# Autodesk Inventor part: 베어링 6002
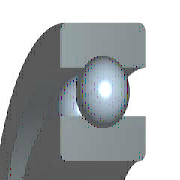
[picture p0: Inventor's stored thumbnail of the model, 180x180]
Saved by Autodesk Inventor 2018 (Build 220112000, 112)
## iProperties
IsCustomPart: 0
Created: 2012-02
Part Number: 베어링 6002
Material: 강철, 연강
Description: 깊은 그루브 볼 베어링
Document SubType Name: Modeling
Standard: KS B 2023
Designer: mduedu
Standards Organization: KS
Language: ko-KR
Size Designation: 6002 - 15 x 32 x 9
Categories: <MemberInstance><Categories><Category DisplayName="샤프트 부품" InternalName="7f7aeb1f-a693-4053-b835-cee3144e0d98" Mnemonic="SHFT"><Category DisplayName="베어링" Inter
Density: 1 g/cm^3
Appearance: 노란색
Author: mduedu
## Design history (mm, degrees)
sketch "스케치" dims "d0" = 4.42 (= -0.26 x WD + 0.26 x BD)
  geometry: L1 (2.29, 11.75)-(6.71, 11.75); L2 (4.5, 11.75)-(4.5, 9.54); L3 (4.5, 11.75)-(4.5, 13.96); L4 (2.858, 10.271)-(0, 10.271); L5 (0, 7.5)-(9, 7.5); L6 (2.858, 13.229)-(0, 13.229); L7 (0, 16)-(9, 16); L8 (9, 7.5)-(9, 10.271); L9 (6.142, 10.271)-(9, 10.271); L10 (6.142, 13.229)-(9, 13.229); L11 (9, 16)-(9, 13.229); L12 (-1.4, 0)-(8.4, 0) reference; L13 (0, -0.3)-(0, 5.3) reference
  constraints: 22 end point, 4 point on line, 2 collinear, 2 perpendicular, 2 symmetric about line, 1 midpoint, 1 parallel, 14 other
  dimensions: "d9" = 15 diameter of L5 L12 (= WD); "d11" = 32 diameter of L7 L12 (= BD); "d12" = 9 distance between parallel lines of L8 L13 (= KB); "d13" = 20.542 diameter of L9 L12 (= 0.326 x BD + 0.674 x WD)
revolve "본체" stored, may be unused: angle "d6" = 90 deg
revolve "볼" stored, may be unused: angle "d7" = 90 deg
pattern_circular "IDS_ARRAYBALL[SIMPL:T]" dims angle "d3" = 360 deg
body "Solid1"
fillet "모깎기1" dims "d1" = 0.3 (= KRS)
other parameters: "WD" = 15 [user parameter; used in 5 equation terms], "BD" = 32 [user parameter; used in 5 equation terms], "KB" = 9 [user parameter; used in 1 equation term], "KRS" = 0.3 [user parameter; used in 1 equation term], "d4" = 0, "d5" = 0, "d8" = 0, "d14" = 0, "d15" = 0, "BBA" = 0 [user parameter], "BC0" = 2850000 [user parameter], "BC" = 5590000 [user parameter], "BR" = 16 (= 0.5 x BD) [user parameter], "WR" = 7.5 (= 0.5 x WD) [user parameter]
